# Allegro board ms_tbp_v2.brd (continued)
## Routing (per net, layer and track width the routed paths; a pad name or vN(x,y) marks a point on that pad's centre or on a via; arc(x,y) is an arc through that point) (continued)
ETH40G_B1_RX1N: length 29.1
  TOP w0.107: J8.21 100.01,5.18 arc(100.02,5.14) 100.04,5.1 100.16,4.98 arc(100.18,4.95) 100.19,4.91 100.19,3.55 v1(100,3.36)
  BOTTOM w0.107: J7.B5 119.97,5.59 arc(119.93,5.57) 119.89,5.56 119.67,5.56 arc(119.27,5.39) 119.11,5 119.11,4.15 arc(118.99,3.87) 118.7,3.75 116.94,3.75 arc(116.31,3.87) 115.77,4.23 113.35,6.65 arc(113,6.88) 112.58,6.97 101.38,6.97 arc(100.54,6.62) 100.19,5.78 100.19,3.81 arc(100.14,3.57) v1(100,3.36)
ETH40G_B1_RX1P: length 29.1
  TOP w0.107: v1(100.82,3.36) 100.63,3.55 100.63,4.91 arc(100.64,4.95) 100.66,4.98 100.78,5.1 arc(100.8,5.14) 100.81,5.18 J8.22
  BOTTOM w0.107: J7.A5 119.97,5.09 arc(119.93,5.11) 119.89,5.12 119.67,5.12 arc(119.58,5.09) 119.54,5 119.54,4.15 arc(119.3,3.56) 118.7,3.31 116.94,3.31 arc(116.14,3.47) 115.47,3.92 113.05,6.34 arc(112.83,6.48) 112.58,6.53 107.04,6.53 106.91,6.4 106.49,6.4 106.36,6.53 105.91,6.53 105.68,6.3 105.27,6.3 105.04,6.53 104.63,6.53 104.4,6.3 103.99,6.3 103.76,6.53 103.35,6.53 103.12,6.3 102.71,6.3 102.48,6.53 101.38,6.53 arc(100.85,6.31) 100.63,5.78 100.63,3.81 arc(100.68,3.57) v1(100.82,3.36)
ETH40G_B1_RX2N: length 43.9
  TOP w0.107: J8.15 102.01,9.64 arc(102.02,9.68) 102.04,9.72 102.16,9.84 arc(102.18,9.87) 102.19,9.91 102.19,12.87 arc(102.14,13.11) v1(102.01,13.31)
  BOTTOM w0.107: v1(102.01,13.31) 102.08,13.39 arc(102.17,13.52) 102.2,13.69 102.2,15.46 arc(102.52,16.22) 103.27,16.53 105.24,16.53 arc(106.18,16.72) 106.98,17.25 arc(109.67,19.04) 112.83,19.67 121.17,19.67 arc(122.2,19.47) 123.07,18.88 arc(123.5,18.24) 123.65,17.47 123.65,5.73 arc(123.71,5.6) 123.83,5.55 arc(123.92,5.57) 124.01,5.63 J7.B3
ETH40G_B1_RX2P: length 43.9
  TOP w0.107: J8.14 102.81,9.64 arc(102.8,9.68) 102.78,9.72 102.66,9.84 arc(102.64,9.87) 102.63,9.91 102.63,12.85 arc(102.68,13.1) v1(102.82,13.31)
  BOTTOM w0.107: J7.A3 124.02,5.04 arc(123.93,5.1) 123.83,5.12 arc(123.4,5.3) 123.22,5.73 123.22,17.47 arc(123.1,18.07) 122.76,18.58 arc(122.03,19.07) 121.17,19.24 117.79,19.24 117.51,18.96 117.08,18.96 116.8,19.24 115.73,19.24 115.47,18.98 115.12,18.98 114.87,19.24 112.83,19.24 arc(109.83,18.64) 107.29,16.94 arc(106.35,16.31) 105.24,16.09 104.43,16.09 104.2,15.86 103.79,15.86 103.56,16.09 103.27,16.09 arc(102.82,15.91) 102.64,15.46 102.64,15.26 102.72,15.18 102.72,14.66 102.64,14.58 102.64,13.69 arc(102.67,13.51) 102.77,13.36 v1(102.82,13.31)
ETH40G_B1_RX3N: length 34.9
  TOP w0.107: J8.24 102.41,5.13 102.59,4.95 102.59,2.3 arc(102.82,1.74) 103.37,1.52 104.02,1.52 arc(104.45,1.6) 104.82,1.85 104.83,1.86 arc(104.93,1.93) 105.06,1.95 105.59,1.95 arc(105.84,1.9) v1(106.05,1.76)
  LYR6 w0.112: v1(106.05,1.76) 106.22,1.94 arc(106.31,1.99) 106.41,2.01 106.62,2.01 arc(106.88,1.96) 107.11,1.81 arc(107.47,1.57) 107.89,1.49 113.17,1.49 arc(113.64,1.58) 114.03,1.85 115.26,3.07 arc(115.5,3.23) 115.78,3.29 126.99,3.29 arc(127.41,3.46) 127.58,3.89 127.58,6.14 arc(127.39,6.6) 126.93,6.79 arc(126.57,6.94) 126.42,7.31 J7.C2
ETH40G_B1_RX3P: length 34.9
  TOP w0.107: J8.25 103.21,5.13 103.03,4.95 103.03,4.74 103.22,4.55 103.22,4.08 103.03,3.89 103.03,2.3 arc(103.13,2.05) 103.37,1.95 104.02,1.95 arc(104.29,2) 104.51,2.16 104.52,2.17 arc(104.77,2.33) 105.06,2.39 105.59,2.39 arc(105.84,2.44) v1(106.05,2.58)
  LYR6 w0.112: v1(106.05,2.58) 106.09,2.54 arc(106.29,2.4) 106.52,2.36 106.62,2.36 arc(107.01,2.28) 107.35,2.05 arc(107.6,1.89) 107.89,1.83 108.51,1.83 108.68,2 108.98,2 109.15,1.83 110.4,1.83 110.63,2.06 111.05,2.06 111.28,1.83 111.69,1.83 111.92,2.06 112.34,2.06 112.57,1.83 113.17,1.83 arc(113.5,1.9) 113.79,2.09 115.02,3.32 arc(115.37,3.55) 115.78,3.63 116.03,3.63 116.26,3.86 116.64,3.86 116.87,3.63 117.29,3.63 117.52,3.86 117.91,3.86 118.14,3.63 118.55,3.63 118.79,3.86 119.17,3.86 119.4,3.63 121.35,3.63 121.58,3.86 122,3.86 122.23,3.63 122.64,3.63 122.87,3.86 123.29,3.86 123.52,3.63 125.05,3.63 125.28,3.86 125.7,3.86 125.93,3.63 126.99,3.63 arc(127.17,3.71) 127.24,3.89 127.24,6.14 arc(127.15,6.36) 126.93,6.45 arc(126.57,6.3) J7.B2
ETH40G_B1_SCL: length 67.8
  TOP w0.102: v1(92.77,35.17) 92.59,35.34 R82.2 ; v1(105.21,13.22) 105.21,12.78 104.66,12.23 104.66,11.37 105.2,10.84 105.2,8.67 J8.11
  LYR3 w0.13: J7.F4 121.24,10.36 121.24,3.82 120.92,3.5 117.77,3.5 116.39,4.88 116.39,5.32 117.6,6.53 117.6,11.29 116.36,12.53 114.18,12.53 113.14,13.57 106.12,13.57 105.77,13.22 v1(105.21,13.22) 105.56,13.58 105.56,19.39 98.66,26.29 98.66,29.27 v1(92.77,35.17)
ETH40G_B1_SDA: length 67.1
  TOP w0.102: J8.12 104.41,10.64 104.31,10.75 104.31,13.25 104.79,13.73 v1(104.79,14.32) ; R81.2 v1(92.67,33.95)
  LYR3 w0.13: v1(92.67,33.95) 98.25,28.36 98.25,25.57 104.79,19.03 v1(104.79,14.32) 104.58,14.1 104.58,12.94 105.02,12.49 105.64,12.49 106.25,13.11 113.12,13.11 114.03,12.21 116.16,12.21 117.28,11.09 117.28,6.63 116.11,5.45 116.11,4.62 117.52,3.21 121.23,3.21 121.58,3.56 121.58,9.3 J7.E4
ETH40G_B1_TX0N: length 17.9
  TOP w0.107: J8.37 112.81,5.18 arc(112.8,5.14) 112.78,5.1 112.66,4.98 arc(112.64,4.95) 112.63,4.91 112.63,4.36 arc(112.69,4.21) 112.84,4.15 113.04,4.15 113.22,4.33 113.53,4.33 113.7,4.15 113.95,4.15 arc(115.03,4.6) 115.48,5.68 115.48,5.8 115.19,6.09 115.19,6.48 115.48,6.77 115.48,6.98 arc(115.42,7.26) v1(115.27,7.49)
  LYR6 w0.112: J7.I6 118.42,15.61 arc(118.3,15.31) 118,15.19 arc(117.43,14.95) 117.2,14.39 117.2,13.07 116.97,12.85 116.97,12.5 117.2,12.27 117.2,11.86 116.96,11.63 116.96,11.22 117.2,10.99 117.2,10.78 arc(117.14,10.51) 116.99,10.28 115.99,9.28 arc(115.64,8.76) 115.52,8.14 115.52,8.09 arc(115.45,7.77) v1(115.27,7.49)
ETH40G_B1_TX0P: length 17.9
  TOP w0.107: J8.36 112.01,5.18 arc(112.02,5.14) 112.04,5.1 112.16,4.98 arc(112.18,4.95) 112.19,4.91 112.19,4.36 arc(112.38,3.91) 112.84,3.72 113.95,3.72 arc(115.34,4.29) 115.91,5.68 115.91,7.09 arc(115.96,7.3) v1(116.08,7.49)
  LYR6 w0.112: J7.H6 118.42,14.42 arc(118.3,14.72) 118,14.85 arc(117.67,14.71) 117.54,14.39 117.54,10.78 arc(117.46,10.38) 117.23,10.04 116.23,9.03 arc(115.95,8.62) 115.86,8.14 115.86,8.02 arc(115.92,7.74) v1(116.08,7.49)
ETH40G_B1_TX1N: length 15
  TOP w0.107: J8.2 112.41,9.64 arc(112.4,9.68) 112.38,9.72 112.26,9.84 arc(112.24,9.87) 112.23,9.91 112.23,11.44 arc(112.28,11.7) v1(112.43,11.93)
  BOTTOM w0.107: J7.C6 117.97,6.89 arc(117.93,6.87) 117.89,6.86 117.79,6.86 arc(117.71,6.89) 117.68,6.96 117.68,8.5 arc(117.48,9) 116.98,9.2 116.51,9.2 116.28,9.43 115.87,9.43 115.64,9.2 115.23,9.2 115,9.43 114.59,9.43 114.36,9.2 113.95,9.2 113.72,9.43 113.31,9.43 113.08,9.2 112.65,9.2 arc(112.36,9.32) 112.24,9.61 112.24,10.15 112.37,10.28 112.37,10.76 112.24,10.89 112.24,11.47 arc(112.29,11.72) v1(112.43,11.93)
ETH40G_B1_TX1P: length 15
  TOP w0.107: J8.3 111.61,9.64 arc(111.62,9.68) 111.64,9.72 111.76,9.84 arc(111.78,9.87) 111.79,9.91 111.79,11.5 arc(111.75,11.73) v1(111.62,11.93)
  BOTTOM w0.107: J7.B6 117.97,6.39 arc(117.93,6.41) 117.89,6.42 117.79,6.42 arc(117.4,6.58) 117.25,6.96 117.25,8.5 arc(117.17,8.69) 116.98,8.77 112.65,8.77 arc(112.06,9.01) 111.81,9.61 111.81,11.47 arc(111.76,11.72) v1(111.62,11.93)
ETH40G_B1_TX2N: length 43.3
  TOP w0.107: J8.34 110.41,5.13 110.23,4.95 110.23,4.58 109.3,3.66 arc(109.27,3.6) 109.25,3.54 109.25,3.38 arc(109.3,3.13) v1(109.45,2.91)
  LYR6 w0.112: J7.C4 122.42,7.31 arc(122.57,6.95) 122.92,6.81 123.04,6.81 arc(123.2,6.87) 123.26,7.02 123.26,17.06 arc(123.03,17.62) 122.46,17.86 121.67,17.86 121.44,17.63 120.87,17.63 120.64,17.86 120.22,17.86 119.99,17.63 119.43,17.63 119.2,17.86 117.79,17.86 arc(117.46,17.79) 117.19,17.6 116.57,16.99 arc(116.36,16.67) 116.28,16.29 116.28,16.08 116.51,15.85 116.51,15.51 116.28,15.28 116.28,14.87 116.47,14.68 116.47,14.26 116.28,14.07 116.28,13.4 arc(115.93,12.57) 115.09,12.22 arc(114.68,12.14) 114.34,11.9 114.24,11.81 arc(114.16,11.68) 114.13,11.54 114.13,11.21 114.36,10.99 114.36,10.66 114.13,10.43 114.13,10.12 114.36,9.89 114.36,9.59 114.13,9.36 114.13,9.13 114.3,8.97 114.3,8.64 114.13,8.47 114.13,7.93 114.13,7.92 114.13,7.15 114.13,7.15 arc(113.82,6.4) 113.08,6.1 112.7,6.1 112.51,5.91 112.09,5.91 111.9,6.1 111.48,6.1 111.27,5.88 110.9,5.88 110.69,6.1 110.47,6.1 arc(110.27,6.01) 110.18,5.81 110.18,5.2 arc(110.1,4.8) 109.88,4.46 109.52,4.11 arc(109.29,3.77) 109.21,3.37 arc(109.26,3.16) 109.37,2.98 v1(109.45,2.91)
ETH40G_B1_TX2P: length 43.3
  TOP w0.107: J8.33 109.61,5.13 109.79,4.95 109.79,4.76 109,3.97 arc(108.86,3.77) 108.82,3.54 108.82,3.36 arc(108.77,3.12) v1(108.63,2.91)
  LYR6 w0.112: J7.B4 122.42,5.97 arc(122.57,6.32) 122.92,6.46 123.04,6.46 arc(123.44,6.63) 123.6,7.02 123.6,17.06 arc(123.27,17.86) 122.46,18.2 117.79,18.2 arc(117.33,18.11) 116.94,17.85 116.33,17.23 arc(116.04,16.8) 115.94,16.29 115.94,13.4 arc(115.69,12.81) 115.09,12.56 arc(114.55,12.45) 114.09,12.15 114,12.05 arc(113.84,11.82) 113.79,11.54 113.79,7.15 arc(113.58,6.65) 113.08,6.44 110.47,6.44 arc(110.02,6.25) 109.84,5.81 109.84,5.2 arc(109.79,4.93) 109.63,4.71 109.28,4.35 arc(108.98,3.9) 108.87,3.37 arc(108.83,3.17) 108.72,3 v1(108.63,2.91)
ETH40G_B1_TX3N: length 43.8
  TOP w0.107: J8.5 110.01,9.64 arc(110,9.68) 109.98,9.72 109.86,9.84 arc(109.84,9.87) 109.83,9.91 109.83,15.42 arc(109.88,15.67) v1(110.02,15.88)
  LYR6 w0.112: J7.B1 128.95,5.51 129.06,5.51 arc(129.45,5.67) 129.61,6.06 129.61,6.35 129.38,6.58 129.38,7.1 129.61,7.33 129.61,8.05 129.38,8.28 129.38,8.76 129.61,8.99 129.61,10.58 129.38,10.81 129.38,11.25 129.61,11.48 129.61,11.89 129.38,12.12 129.38,12.56 129.61,12.79 129.61,15.54 arc(129.51,16.04) 129.23,16.46 126.55,19.14 arc(126.3,19.31) 126,19.37 124.77,19.37 124.54,19.14 124.02,19.14 123.79,19.37 119.44,19.37 119.21,19.14 118.65,19.14 118.42,19.37 116.27,19.37 116.04,19.14 115.63,19.14 115.4,19.37 114.43,19.37 114.2,19.14 113.79,19.14 113.56,19.37 113.08,19.37 arc(112.32,19.22) 111.68,18.79 111.05,18.16 111.05,18.01 110.75,17.7 110.6,17.7 109.84,16.94 arc(109.8,16.88) 109.78,16.8 109.78,16.44 arc(109.84,16.14) v1(110.02,15.88)
ETH40G_B1_TX3P: length 43.8
  TOP w0.107: J8.6 109.21,9.64 arc(109.22,9.68) 109.24,9.72 109.36,9.84 arc(109.38,9.87) 109.39,9.91 109.39,15.42 arc(109.34,15.67) v1(109.2,15.88)
  LYR6 w0.112: J7.A1 128.95,5.17 129.06,5.17 arc(129.69,5.43) 129.95,6.06 129.95,15.54 arc(129.83,16.17) 129.47,16.7 126.79,19.38 arc(126.43,19.63) 126,19.71 113.08,19.71 arc(112.19,19.53) 111.44,19.03 109.6,17.19 arc(109.48,17.01) 109.44,16.8 109.44,16.44 arc(109.38,16.14) v1(109.2,15.88)
ETH40G_B2_INT_N: length 57
  TOP w0.102: v1(313.19,36.77) R64.2 ; v1(326.47,4.81) 326.61,4.94 J20.28
  LYR3 w0.13: v1(319.45,4.37) 319.45,4.47 319.03,4.89 319.03,11.99 320.1,13.05 320.1,23.33 318.85,24.57 317.1,24.57 316.31,25.36 313.72,25.36 310.34,28.74 310.34,29.73 309.46,30.62 309.46,35.52 309.96,36.03 311.97,36.03 312.71,36.77 v1(313.19,36.77)
  LYR6 w0.13: v1(319.45,4.37) 319.45,4.75 319.89,5.19 319.89,7.05 320.1,7.26 325.99,7.26 326.21,7.04 326.21,5.07 v1(326.47,4.81)
ETH40G_B2_LPMODE: length 67.6
  TOP w0.102: v1(329.01,4.32) J20.31 ; R70.2 308.38,32.47 v1(307.47,32.47) ; R65.1 v1(309.99,38.16)
  LYR3 w0.13: v1(319.45,3.5) 319.33,3.62 318.32,3.62 316.44,5.5 316.44,13.58 319.34,16.47 319.34,22.87 318.09,24.12 316.28,24.12 315.42,24.98 312.27,24.98 309.9,27.36 309.9,28.3 308.85,29.35 308.85,31.1 v1(307.47,32.47) 307.68,32.68 307.68,37.22 308.62,38.16 v1(309.99,38.16)
  LYR6 w0.13: v1(319.45,3.5) 319.45,3.51 318.84,4.13 318.84,4.58 319.61,5.36 319.61,7.22 319.95,7.56 328.04,7.56 328.63,6.97 328.63,5.2 329.01,4.83 v1(329.01,4.32)
ETH40G_B2_MODPRS_N: length 61.2
  TOP w0.102: R66.1 v1(340.8,37.93) ; v1(337.76,5.56) 337.76,4.69 336.05,2.97 333.9,2.97 332.48,1.54 328.86,1.54 328.38,2.02 328.38,3.38 327.76,4 v1(326.06,4) 325.81,4.25 J20.27
  LYR3 w0.13: v1(340.8,37.93) 341.66,38.8 341.66,39.56 341.33,39.89 339.58,39.89 334.91,35.22 334.91,20.49 338.69,16.7 338.69,6.49 v1(337.76,5.56)
ETH40G_B2_MODSEL_N: length 42.8
  TOP w0.102: v1(313.14,40.96) R62.2 R63.1 ; v1(327.56,18.39) 327.56,15.74 329.39,13.91 329.39,11.95 328.61,11.17 J20.8
  LYR3 w0.13: v1(313.14,40.96) 313.88,40.96 315.68,39.15 315.68,34.63 324.05,26.26 324.05,20.85 326.5,18.39 v1(327.56,18.39)
ETH40G_B2_PRES_N: length 29.2
  TOP w0.102: R66.2 343.82,37.93 v1(343.87,37.88)
  LYR3 w0.13: v1(343.87,37.88) 342.25,37.88 338.87,34.51 338.87,21.73 342.37,18.22 342.37,15.39 J19.H5
ETH40G_B2_RESET_N: length 47.4
  TOP w0.102: R69.2 v1(313.39,39.56) ; J20.9 327.81,11.15 326.65,12.31 326.19,12.31 v1(325.83,12.66) ; R61.2 v1(310.2,32.58)
  LYR3 w0.13: v1(325.83,12.66) 325.83,13.69 324.93,14.6 323.02,14.6 320.83,16.78 320.83,20.86 320.78,20.91 320.78,25.79 319.27,27.31 312.54,27.31 311.49,28.36 311.49,31.29 v1(310.2,32.58) 310.2,32.61 311.39,33.79 311.39,34.58 312.96,36.15 313.39,36.15 313.9,36.66 313.9,39.05 v1(313.39,39.56)
ETH40G_B2_RX0N: length 36.2
  TOP w0.107: J20.18 320.61,9.64 arc(320.62,9.68) 320.64,9.72 320.76,9.84 arc(320.78,9.87) 320.79,9.91 320.79,10.99 arc(320.74,11.24) v1(320.6,11.45)
  BOTTOM w0.107: J19.F6 339.87,11.09 arc(339.91,11.07) 339.95,11.06 340.05,11.06 arc(340.15,11.1) 340.19,11.19 340.19,17.17 arc(340.12,17.52) 339.92,17.82 arc(339.45,18.02) 338.97,17.82 arc(338.32,17.39) 337.56,17.23 335.45,17.23 arc(334.87,17.12) 334.37,16.79 334.21,16.62 334.21,16.33 333.92,16.04 333.62,16.04 333.33,15.75 333.33,15.46 333.04,15.17 332.75,15.17 332.46,14.88 332.46,14.58 332.17,14.29 331.88,14.29 331.58,14 331.58,13.71 331.29,13.42 331,13.42 328.46,10.88 arc(325.89,9.16) 322.86,8.56 322.24,8.56 arc(321.22,8.98) 320.79,10.01 320.79,10.99 arc(320.74,11.24) v1(320.6,11.45)
ETH40G_B2_RX0P: length 36.2
  TOP w0.107: J20.17 321.41,9.64 arc(321.4,9.68) 321.38,9.72 321.26,9.84 arc(321.24,9.87) 321.23,9.91 321.23,10.99 arc(321.28,11.24) v1(321.42,11.45)
  BOTTOM w0.107: J19.E6 339.87,10.59 arc(339.91,10.61) 339.95,10.62 340.05,10.62 arc(340.46,10.79) 340.62,11.19 340.62,17.17 arc(340.52,17.69) 340.23,18.13 arc(339.45,18.45) 338.66,18.13 arc(338.16,17.79) 337.56,17.67 335.45,17.67 arc(334.7,17.52) 334.07,17.1 328.15,11.19 arc(325.73,9.56) 322.86,8.99 322.24,8.99 arc(321.52,9.29) 321.23,10.01 321.23,10.99 arc(321.28,11.24) v1(321.42,11.45)
ETH40G_B2_RX1N: length 29.1
  TOP w0.107: J20.21 321.01,5.18 arc(321.02,5.14) 321.04,5.1 321.16,4.98 arc(321.18,4.95) 321.19,4.91 321.19,3.55 v1(321,3.36)
  BOTTOM w0.107: J19.B5 340.97,5.59 arc(340.93,5.57) 340.89,5.56 340.67,5.56 arc(340.27,5.39) 340.11,5 340.11,4.15 arc(339.99,3.87) 339.7,3.75 337.94,3.75 arc(337.31,3.87) 336.77,4.23 334.35,6.65 arc(334,6.88) 333.58,6.97 322.38,6.97 arc(321.54,6.62) 321.19,5.78 321.19,3.81 arc(321.14,3.57) v1(321,3.36)
ETH40G_B2_RX1P: length 29.1
  TOP w0.107: v1(321.82,3.36) 321.63,3.55 321.63,4.91 arc(321.64,4.95) 321.66,4.98 321.78,5.1 arc(321.8,5.14) 321.81,5.18 J20.22
  BOTTOM w0.107: J19.A5 340.97,5.09 arc(340.93,5.11) 340.89,5.12 340.67,5.12 arc(340.58,5.09) 340.54,5 340.54,4.15 arc(340.3,3.56) 339.7,3.31 337.94,3.31 arc(337.14,3.47) 336.47,3.92 334.05,6.34 arc(333.83,6.48) 333.58,6.53 328.04,6.53 327.91,6.4 327.49,6.4 327.36,6.53 326.91,6.53 326.68,6.3 326.27,6.3 326.04,6.53 325.63,6.53 325.4,6.3 324.99,6.3 324.76,6.53 324.35,6.53 324.12,6.3 323.71,6.3 323.48,6.53 322.38,6.53 arc(321.85,6.31) 321.63,5.78 321.63,3.81 arc(321.68,3.57) v1(321.82,3.36)
ETH40G_B2_RX2N: length 43.9
  TOP w0.107: J20.15 323.01,9.64 arc(323.02,9.68) 323.04,9.72 323.16,9.84 arc(323.18,9.87) 323.19,9.91 323.19,12.87 arc(323.14,13.11) v1(323.01,13.31)
  BOTTOM w0.107: v1(323.01,13.31) 323.08,13.39 arc(323.17,13.52) 323.2,13.69 323.2,15.46 arc(323.52,16.22) 324.27,16.53 326.24,16.53 arc(327.18,16.72) 327.98,17.25 arc(330.67,19.04) 333.83,19.67 342.17,19.67 arc(343.2,19.47) 344.07,18.88 arc(344.5,18.24) 344.65,17.47 344.65,5.73 arc(344.71,5.6) 344.83,5.55 arc(344.92,5.57) 345.01,5.63 J19.B3
ETH40G_B2_RX2P: length 43.9
  TOP w0.107: J20.14 323.81,9.64 arc(323.8,9.68) 323.78,9.72 323.66,9.84 arc(323.64,9.87) 323.63,9.91 323.63,12.85 arc(323.68,13.1) v1(323.82,13.31)
  BOTTOM w0.107: v1(323.82,13.31) 323.77,13.36 arc(323.67,13.51) 323.64,13.69 323.64,14.58 323.72,14.66 323.72,15.18 323.64,15.26 323.64,15.46 arc(323.82,15.91) 324.27,16.09 324.56,16.09 324.79,15.86 325.2,15.86 325.43,16.09 326.24,16.09 arc(327.35,16.31) 328.29,16.94 arc(330.83,18.64) 333.83,19.24 335.87,19.24 336.12,18.98 336.47,18.98 336.73,19.24 337.8,19.24 338.08,18.96 338.51,18.96 338.79,19.24 342.17,19.24 arc(343.03,19.07) 343.76,18.58 arc(344.1,18.07) 344.22,17.47 344.22,5.73 arc(344.4,5.3) 344.83,5.12 arc(344.93,5.1) 345.02,5.04 J19.A3
ETH40G_B2_RX3N: length 34.9
  TOP w0.107: J20.24 323.41,5.13 323.59,4.95 323.59,2.3 arc(323.82,1.74) 324.37,1.52 325.02,1.52 arc(325.45,1.6) 325.82,1.85 325.83,1.86 arc(325.93,1.93) 326.06,1.95 326.59,1.95 arc(326.84,1.9) v1(327.05,1.76)
  LYR6 w0.112: J19.C2 347.42,7.31 arc(347.57,6.94) 347.93,6.79 arc(348.39,6.6) 348.58,6.14 348.58,3.89 arc(348.41,3.46) 347.99,3.29 336.78,3.29 arc(336.5,3.23) 336.26,3.07 335.03,1.85 arc(334.64,1.58) 334.17,1.49 328.89,1.49 arc(328.47,1.57) 328.11,1.81 arc(327.88,1.96) 327.62,2.01 327.41,2.01 arc(327.31,1.99) 327.22,1.94 v1(327.05,1.76)
ETH40G_B2_RX3P: length 34.9
  TOP w0.107: J20.25 324.21,5.13 324.03,4.95 324.03,4.74 324.22,4.55 324.22,4.08 324.03,3.89 324.03,2.3 arc(324.13,2.05) 324.37,1.95 325.02,1.95 arc(325.29,2) 325.51,2.16 325.52,2.17 arc(325.77,2.33) 326.06,2.39 326.59,2.39 arc(326.84,2.44) v1(327.05,2.58)
  LYR6 w0.112: v1(327.05,2.58) 327.09,2.54 arc(327.29,2.4) 327.52,2.36 327.62,2.36 arc(328.01,2.28) 328.35,2.05 arc(328.6,1.89) 328.89,1.83 329.51,1.83 329.68,2 329.98,2 330.15,1.83 331.4,1.83 331.63,2.06 332.05,2.06 332.28,1.83 332.69,1.83 332.92,2.06 333.34,2.06 333.57,1.83 334.17,1.83 arc(334.5,1.9) 334.79,2.09 336.02,3.32 arc(336.37,3.55) 336.78,3.63 337.03,3.63 337.26,3.86 337.64,3.86 337.87,3.63 338.29,3.63 338.52,3.86 338.91,3.86 339.14,3.63 339.55,3.63 339.79,3.86 340.17,3.86 340.4,3.63 342.35,3.63 342.58,3.86 343,3.86 343.23,3.63 343.64,3.63 343.87,3.86 344.29,3.86 344.52,3.63 346.05,3.63 346.28,3.86 346.7,3.86 346.93,3.63 347.99,3.63 arc(348.17,3.71) 348.24,3.89 348.24,6.14 arc(348.15,6.36) 347.93,6.45 arc(347.57,6.3) J19.B2
ETH40G_B2_SCL: length 73.9
  TOP w0.102: v1(313.49,35.37) R68.2 ; v1(323.5,18.6) 323.5,18.49 325.2,16.79 325.2,12.51 326.21,11.5 J20.11
  LYR3 w0.13: J19.F4 342.42,10.54 342.42,4.1 341.97,3.64 337.75,3.64 337.18,4.21 337.18,5.7 338.24,6.75 338.24,13.47 336.38,15.33 333.92,15.33 333.23,14.64 328.99,14.64 326.17,17.46 324.64,17.46 v1(323.5,18.6) 322.95,19.14 322.95,25.98 313.56,35.37 v1(313.49,35.37)
ETH40G_B2_SDA: length 69.4
  TOP w0.102: v1(313.06,33.97) R67.2 ; J20.12 325.41,11.79 324.95,12.26 324.95,14.44 323.46,15.93 v1(323.46,17.69)
  LYR3 w0.13: v1(313.06,33.97) 313.64,33.97 321.82,25.79 321.82,19.32 v1(323.46,17.69) 325.75,15.39 326.69,15.39 327.75,14.34 333.2,14.34 335.15,12.4 335.15,5.46 337.32,3.29 343.72,3.29 344.46,4.03 344.46,9.1 J19.E4
ETH40G_B2_TX0N: length 17.9
  TOP w0.107: J20.37 333.81,5.18 arc(333.8,5.14) 333.78,5.1 333.66,4.98 arc(333.64,4.95) 333.63,4.91 333.63,4.36 arc(333.69,4.21) 333.84,4.15 334.04,4.15 334.22,4.33 334.53,4.33 334.7,4.15 334.95,4.15 arc(336.03,4.6) 336.48,5.68 336.48,5.8 336.19,6.09 336.19,6.48 336.48,6.77 336.48,6.98 arc(336.42,7.26) v1(336.27,7.49)
  LYR6 w0.112: J19.I6 339.42,15.61 arc(339.3,15.31) 339,15.19 arc(338.43,14.95) 338.2,14.39 338.2,13.07 337.97,12.85 337.97,12.5 338.2,12.27 338.2,11.86 337.96,11.63 337.96,11.22 338.2,10.99 338.2,10.78 arc(338.14,10.51) 337.99,10.28 336.99,9.28 arc(336.64,8.76) 336.52,8.14 336.52,8.09 arc(336.45,7.77) v1(336.27,7.49)
ETH40G_B2_TX0P: length 17.9
  TOP w0.107: J20.36 333.01,5.18 arc(333.02,5.14) 333.04,5.1 333.16,4.98 arc(333.18,4.95) 333.19,4.91 333.19,4.36 arc(333.38,3.91) 333.84,3.72 334.95,3.72 arc(336.34,4.29) 336.91,5.68 336.91,7.09 arc(336.96,7.3) v1(337.08,7.49)
  LYR6 w0.112: J19.H6 339.42,14.42 arc(339.3,14.72) 339,14.85 arc(338.67,14.71) 338.54,14.39 338.54,10.78 arc(338.46,10.38) 338.23,10.04 337.23,9.03 arc(336.95,8.62) 336.86,8.14 336.86,8.02 arc(336.92,7.74) v1(337.08,7.49)
ETH40G_B2_TX1N: length 15
  TOP w0.107: J20.2 333.41,9.64 arc(333.4,9.68) 333.38,9.72 333.26,9.84 arc(333.24,9.87) 333.23,9.91 333.23,11.44 arc(333.28,11.7) v1(333.43,11.93)
  BOTTOM w0.107: J19.C6 338.97,6.89 arc(338.93,6.87) 338.89,6.86 338.79,6.86 arc(338.71,6.89) 338.68,6.96 338.68,8.5 arc(338.48,9) 337.98,9.2 337.51,9.2 337.28,9.43 336.87,9.43 336.64,9.2 336.23,9.2 336,9.43 335.59,9.43 335.36,9.2 334.95,9.2 334.72,9.43 334.31,9.43 334.08,9.2 333.65,9.2 arc(333.36,9.32) 333.24,9.61 333.24,10.15 333.37,10.28 333.37,10.76 333.24,10.89 333.24,11.47 arc(333.29,11.72) v1(333.43,11.93)
ETH40G_B2_TX1P: length 15
  TOP w0.107: J20.3 332.61,9.64 arc(332.62,9.68) 332.64,9.72 332.76,9.84 arc(332.78,9.87) 332.79,9.91 332.79,11.5 arc(332.75,11.73) v1(332.62,11.93)
  BOTTOM w0.107: J19.B6 338.97,6.39 arc(338.93,6.41) 338.89,6.42 338.79,6.42 arc(338.4,6.58) 338.25,6.96 338.25,8.5 arc(338.17,8.69) 337.98,8.77 333.65,8.77 arc(333.06,9.01) 332.81,9.61 332.81,11.47 arc(332.76,11.72) v1(332.62,11.93)
ETH40G_B2_TX2N: length 43.3
  TOP w0.107: J20.34 331.41,5.13 331.23,4.95 331.23,4.58 330.3,3.66 arc(330.27,3.6) 330.25,3.54 330.25,3.38 arc(330.3,3.13) v1(330.45,2.91)
  LYR6 w0.112: v1(330.45,2.91) 330.37,2.98 arc(330.26,3.16) 330.21,3.37 arc(330.29,3.77) 330.52,4.11 330.88,4.46 arc(331.1,4.8) 331.18,5.2 331.18,5.81 arc(331.27,6.01) 331.47,6.1 331.69,6.1 331.9,5.88 332.27,5.88 332.48,6.1 332.9,6.1 333.09,5.91 333.51,5.91 333.7,6.1 334.08,6.1 arc(334.82,6.4) 335.13,7.15 335.13,7.15 335.13,7.92 335.13,7.93 335.13,8.47 335.3,8.64 335.3,8.97 335.13,9.13 335.13,9.36 335.36,9.59 335.36,9.89 335.13,10.12 335.13,10.43 335.36,10.66 335.36,10.99 335.13,11.21 335.13,11.54 arc(335.16,11.68) 335.24,11.81 335.34,11.9 arc(335.68,12.14) 336.09,12.22 arc(336.93,12.57) 337.28,13.4 337.28,14.07 337.47,14.26 337.47,14.68 337.28,14.87 337.28,15.28 337.51,15.51 337.51,15.85 337.28,16.08 337.28,16.29 arc(337.36,16.67) 337.57,16.99 338.19,17.6 arc(338.46,17.79) 338.79,17.86 340.2,17.86 340.43,17.63 340.99,17.63 341.22,17.86 341.64,17.86 341.87,17.63 342.44,17.63 342.67,17.86 343.46,17.86 arc(344.03,17.62) 344.26,17.06 344.26,7.02 arc(344.2,6.87) 344.04,6.81 343.92,6.81 arc(343.57,6.95) 343.42,7.31 J19.C4
ETH40G_B2_TX2P: length 43.3
  TOP w0.107: J20.33 330.61,5.13 330.79,4.95 330.79,4.76 330,3.97 arc(329.86,3.77) 329.82,3.54 329.82,3.36 arc(329.77,3.12) v1(329.63,2.91)
  LYR6 w0.112: J19.B4 343.42,5.97 arc(343.57,6.32) 343.92,6.46 344.04,6.46 arc(344.44,6.63) 344.6,7.02 344.6,17.06 arc(344.27,17.86) 343.46,18.2 338.79,18.2 arc(338.33,18.11) 337.94,17.85 337.33,17.23 arc(337.04,16.8) 336.94,16.29 336.94,13.4 arc(336.69,12.81) 336.09,12.56 arc(335.55,12.45) 335.09,12.15 335,12.05 arc(334.84,11.82) 334.79,11.54 334.79,7.15 arc(334.58,6.65) 334.08,6.44 331.47,6.44 arc(331.02,6.25) 330.84,5.81 330.84,5.2 arc(330.79,4.93) 330.63,4.71 330.28,4.35 arc(329.98,3.9) 329.87,3.37 arc(329.83,3.17) 329.72,3 v1(329.63,2.91)
ETH40G_B2_TX3N: length 43.8
  TOP w0.107: J20.5 331.01,9.64 arc(331,9.68) 330.98,9.72 330.86,9.84 arc(330.84,9.87) 330.83,9.91 330.83,15.42 arc(330.88,15.67) v1(331.02,15.88)
  LYR6 w0.112: J19.B1 349.95,5.51 350.06,5.51 arc(350.45,5.67) 350.61,6.06 350.61,6.35 350.38,6.58 350.38,7.1 350.61,7.33 350.61,8.05 350.38,8.28 350.38,8.76 350.61,8.99 350.61,10.58 350.38,10.81 350.38,11.25 350.61,11.48 350.61,11.89 350.38,12.12 350.38,12.56 350.61,12.79 350.61,15.54 arc(350.51,16.04) 350.23,16.46 347.55,19.14 arc(347.3,19.31) 347,19.37 345.77,19.37 345.54,19.14 345.02,19.14 344.79,19.37 340.44,19.37 340.21,19.14 339.65,19.14 339.42,19.37 337.27,19.37 337.04,19.14 336.63,19.14 336.4,19.37 335.43,19.37 335.2,19.14 334.79,19.14 334.56,19.37 334.08,19.37 arc(333.32,19.22) 332.68,18.79 332.05,18.16 332.05,18.01 331.75,17.7 331.6,17.7 330.84,16.94 arc(330.8,16.88) 330.78,16.8 330.78,16.44 arc(330.84,16.14) v1(331.02,15.88)
ETH40G_B2_TX3P: length 43.8
  TOP w0.107: J20.6 330.21,9.64 arc(330.22,9.68) 330.24,9.72 330.36,9.84 arc(330.38,9.87) 330.39,9.91 330.39,15.42 arc(330.34,15.67) v1(330.2,15.88)
  LYR6 w0.112: J19.A1 349.95,5.17 350.06,5.17 arc(350.69,5.43) 350.95,6.06 350.95,15.54 arc(350.83,16.17) 350.47,16.7 347.79,19.38 arc(347.43,19.63) 347,19.71 334.08,19.71 arc(333.19,19.53) 332.44,19.03 330.6,17.19 arc(330.48,17.01) 330.44,16.8 330.44,16.44 arc(330.38,16.14) v1(330.2,15.88)
JBOD_B1_MATED_N: length 14.8
  TOP w0.102: R1.2 177.74,5.41 175.9,3.57 170.7,3.57 169.6,4.66 169.6,5.12 J11.B4
JBOD_B2_MATED_N: length 15.1
  TOP w0.102: J23.B4 390.59,5.13 390.6,5.11 390.6,4.43 391.45,3.58 396.45,3.58 396.81,3.94 396.81,4.4 397.56,5.15 R71.2
MEZZ_B1_EN: length 41
  TOP w0.127: J2.157 v1(47.38,31.74)
  LYR4 w0.13: J1.H5 22.89,15.43 22.89,26.86 24.75,28.71 38.16,28.71 42.22,32.78 45.85,32.78 46.89,31.74 v1(47.38,31.74)
MEZZ_B1_SCL: length 40.6
  TOP w0.127: J2.156 v1(46.11,31.74)
  LYR4 w0.13: v1(46.11,31.74) 45.38,32.47 44.51,32.47 44.1,32.07 44.1,31.37 43.82,31.09 41.42,31.09 38.5,28.17 25.29,28.17 23.15,26.02 23.15,14.31 22,13.17 J1.G5
MEZZ_B1_SDA: length 38
  TOP w0.127: J2.158 v1(48.65,31.74)
  LYR4 w0.13: v1(48.65,31.74) 48.6,31.74 48.09,31.23 44.79,31.23 44.23,30.67 44.23,30.21 43.88,29.86 41.31,29.86 39.29,27.83 26.41,27.83 24.9,26.33 24.9,16.74 J1.I4
MEZZ_B2_EN: length 41
  TOP w0.127: J14.157 v1(268.38,31.74)
  LYR4 w0.13: J13.H5 243.89,15.43 243.89,26.86 245.75,28.71 259.16,28.71 263.22,32.78 266.85,32.78 267.89,31.74 v1(268.38,31.74)
MEZZ_B2_SCL: length 40.6
  TOP w0.127: J14.156 v1(267.11,31.74)
  LYR4 w0.13: J13.G5 243,13.17 244.15,14.31 244.15,26.02 246.29,28.17 259.5,28.17 262.42,31.09 264.82,31.09 265.1,31.37 265.1,32.07 265.51,32.47 266.38,32.47 v1(267.11,31.74)
MEZZ_B2_SDA: length 38
  TOP w0.127: J14.158 v1(269.65,31.74)
  LYR4 w0.13: J13.I4 245.9,16.74 245.9,26.33 247.41,27.83 260.29,27.83 262.31,29.86 264.88,29.86 265.23,30.21 265.23,30.67 265.8,31.24 269.1,31.24 269.6,31.74 v1(269.65,31.74)
MEZZ_PRESENT_B1_N: length 48.5
  TOP w0.127: J2.160 v1(51.19,31.74)
  LYR4 w0.13: v1(51.19,31.74) 50.58,32.35 46.84,32.35 46.06,33.13 41.87,33.13 37.93,29.2 22.31,29.2 18.98,25.87 18.98,15.46 20,14.44 J1.H6
MEZZ_PRESENT_B2_N: length 48.5
  TOP w0.127: J14.160 v1(272.19,31.74)
  LYR4 w0.13: J13.H6 241,14.44 239.98,15.46 239.98,25.87 243.31,29.2 258.93,29.2 262.87,33.13 267.06,33.13 267.84,32.35 271.58,32.35 v1(272.19,31.74)
PCIE_B2T_B1_TX_DN<0>: length 46.1
  TOP w0.127: J2.125 v1(47.38,26.66)
  BOTTOM w0.127: J1.L8 16.55,19.49 16.67,19.49 16.85,19.67 16.85,26.23 23.58,32.96 34.86,32.96 41.23,26.58 42.27,26.58 43.13,27.44 45.23,27.44 45.64,27.04 45.64,26.32 45.79,26.18 46.9,26.18 v1(47.38,26.66)
PCIE_B2T_B1_TX_DN<1>: length 46.1
  TOP w0.127: J2.110 v1(48.65,24.12)
  BOTTOM w0.127: J1.K7 18.55,18.19 18.76,18.19 18.85,18.29 18.85,26.33 24.26,31.74 34.02,31.74 40.85,24.9 46.5,24.9 46.91,24.5 46.91,23.78 47.06,23.64 48.17,23.64 v1(48.65,24.12)
PCIE_B2T_B1_TX_DN<2>: length 41.3
  TOP w0.127: J2.93 v1(47.38,21.58)
  BOTTOM w0.127: J1.L6 20.55,19.49 20.67,19.49 20.86,19.67 20.86,24.81 20.86,24.82 20.86,26.12 25.23,30.49 33.41,30.49 40.9,23 43.47,23 44.12,22.36 45.23,22.36 45.64,21.96 45.64,21.24 45.79,21.1 46.9,21.1 v1(47.38,21.58)
PCIE_B2T_B1_TX_DN<3>: length 42.4
  TOP w0.127: J2.78 v1(48.65,19.04)
  BOTTOM w0.127: v1(48.65,19.04) 48.17,18.56 47.06,18.56 46.91,18.7 46.91,19.42 46.5,19.82 41.26,19.82 38.44,22.64 38.44,23.33 32.54,29.22 32.54,29.22 31.53,29.22 31.53,29.22 25.84,29.22 23.02,26.4 22.84,26.23 22.84,18.36 22.67,18.19 22.55,18.19 J1.K5
PCIE_B2T_B1_TX_DN<4>: length 37.8
  TOP w0.127: J2.61 v1(47.38,16.5)
  BOTTOM w0.127: J1.L4 24.55,19.49 24.66,19.49 24.85,19.68 24.85,25.95 26.91,28 31.63,28 35.97,23.66 35.97,22.69 40.75,17.92 42.95,17.92 43.59,17.28 45.23,17.28 45.64,16.88 45.64,16.16 45.79,16.02 46.9,16.02 v1(47.38,16.5)
PCIE_B2T_B1_TX_DN<5>: length 38.6
  TOP w0.127: J2.46 v1(48.65,13.96)
  BOTTOM w0.127: v1(48.65,13.96) 48.17,13.48 47.06,13.48 46.91,13.62 46.91,14.34 46.5,14.74 43.3,14.74 41.5,16.54 40.29,16.54 33.79,23.04 33.79,23.99 31,26.78 27.53,26.78 26.86,26.11 26.86,26.1 26.86,26.1 26.86,18.35 26.69,18.19 26.55,18.19 J1.K3
PCIE_B2T_B1_TX_DN<6>: length 33.4
  TOP w0.127: J2.29 v1(47.38,11.42)
  BOTTOM w0.127: v1(47.38,11.42) 46.9,10.94 45.79,10.94 45.64,11.08 45.64,11.8 45.23,12.2 44.4,12.2 43.75,12.85 41.99,12.85 41.7,13.15 41.7,13.37 31.14,23.92 31.14,24.81 30.47,25.48 30.01,25.48 30,25.49 29.47,25.49 28.86,24.87 28.86,19.61 28.74,19.49 28.55,19.49 J1.L2
PCIE_B2T_B1_TX_DN<7>: length 24.9
  TOP w0.127: J2.14 v1(48.65,8.88)
  BOTTOM w0.127: v1(48.65,8.88) 48.17,8.4 47.06,8.4 46.91,8.54 46.91,9.26 46.5,9.66 42.8,9.66 40.52,11.94 40.52,12.7 37.66,15.56 35.29,15.56 32.65,18.19 30.55,18.19 J1.K1
PCIE_B2T_B1_TX_DN<8>: length 44.5
  TOP w0.127: J2.127 v1(49.92,26.66)
  LYR6 w0.127: v1(49.92,26.66) 49.43,26.17 48.28,26.17 48.17,26.29 48.17,27.08 47.79,27.45 43.23,27.45 42.35,26.57 40.2,26.57 34.77,32 21.27,32 16.87,27.6 16.87,23.89 16.67,23.69 16.55,23.69 J1.O8
PCIE_B2T_B1_TX_DN<9>: length 44.2
  TOP w0.127: J2.112 v1(51.19,24.12)
  LYR6 w0.127: J1.N7 18.55,22.39 18.76,22.39 18.84,22.46 18.84,26.98 22.82,30.96 34.34,30.96 40.39,24.91 49.06,24.91 49.44,24.54 49.44,23.75 49.55,23.63 50.7,23.63 v1(51.19,24.12)
PCIE_B2T_B1_TX_DN<10>: length 39.5
  TOP w0.127: J2.95 v1(49.92,21.58)
  LYR6 w0.127: v1(49.92,21.58) 49.43,21.09 48.28,21.09 48.17,21.21 48.17,22 47.79,22.37 43.45,22.37 42.82,23 40.8,23 37.09,26.71 35.51,26.71 32.3,29.92 24.4,29.92 20.85,26.37 20.85,23.74 20.79,23.69 20.55,23.69 J1.O6
PCIE_B2T_B1_TX_DN<11>: length 40.2
  TOP w0.127: J2.80 v1(51.19,19.04)
  LYR6 w0.127: v1(51.19,19.04) 50.7,18.55 49.55,18.55 49.44,18.67 49.44,19.46 49.06,19.83 40.87,19.83 31.82,28.88 25.42,28.88 22.85,26.31 22.85,22.5 22.74,22.39 22.55,22.39 J1.N5
PCIE_B2T_B1_TX_DN<12>: length 36.3
  TOP w0.127: J2.63 v1(49.92,16.5)
  LYR6 w0.127: J1.O4 24.55,23.69 24.7,23.69 24.86,23.84 24.86,26.35 26.33,27.81 31.36,27.81 35.24,23.94 35.24,23.06 40.37,17.92 43.16,17.92 43.79,17.29 47.79,17.29 48.17,16.92 48.17,16.13 48.28,16.01 49.43,16.01 v1(49.92,16.5)
PCIE_B2T_B1_TX_DN<13>: length 38.1
  TOP w0.127: J2.48 v1(51.19,13.96)
  LYR6 w0.127: v1(51.19,13.96) 50.7,13.47 49.55,13.47 49.44,13.59 49.44,14.38 49.06,14.75 40.06,14.75 34.07,20.74 34.07,23.53 30.83,26.77 27.53,26.77 26.87,26.11 26.87,22.47 26.79,22.39 26.55,22.39 J1.N3
PCIE_B2T_B1_TX_DN<14>: length 33.4
  TOP w0.127: J2.31 v1(49.92,11.42)
  LYR6 w0.127: v1(49.92,11.42) 49.43,10.93 48.28,10.93 48.17,11.05 48.17,11.84 47.79,12.21 43.69,12.21 43.07,12.83 39.41,12.83 32.76,19.48 32.76,23.27 30.53,25.5 29.32,25.5 28.81,24.99 28.81,23.81 28.68,23.69 28.55,23.69 J1.O2
PCIE_B2T_B1_TX_DN<15>: length 37.9
  TOP w0.127: J2.16 v1(51.19,8.88)
  LYR6 w0.127: v1(51.19,8.88) 50.7,8.39 49.52,8.39 49.15,8.03 49.15,7.05 48.52,6.41 34.15,6.41 31.67,8.9 31.67,16.51 31.5,16.68 31.31,16.87 31.31,21.88 30.8,22.39 30.55,22.39 J1.N1
PCIE_B2T_B1_TX_DP<0>: length 46.1
  TOP w0.127: J2.117 v1(47.38,25.39)
  BOTTOM w0.127: v1(47.38,25.39) 46.9,25.87 45.66,25.87 45.33,26.2 45.33,26.91 45.11,27.14 43.25,27.14 42.39,26.28 41.1,26.28 34.73,32.65 23.7,32.65 17.15,26.1 17.15,19.54 16.8,19.19 16.55,19.19 J1.K8
PCIE_B2T_B1_TX_DP<1>: length 46.1
  TOP w0.127: J2.102 v1(48.65,22.85)
  BOTTOM w0.127: J1.J7 18.55,17.89 18.88,17.89 19.16,18.16 19.16,26.2 24.39,31.43 33.89,31.43 40.73,24.6 46.38,24.6 46.6,24.37 46.6,23.66 46.93,23.33 48.17,23.33 v1(48.65,22.85)
PCIE_B2T_B1_TX_DP<2>: length 41.3
  TOP w0.127: J2.85 v1(47.38,20.31)
  BOTTOM w0.127: v1(47.38,20.31) 46.9,20.79 45.66,20.79 45.33,21.12 45.33,21.83 45.11,22.06 43.99,22.06 43.35,22.7 40.77,22.7 33.28,30.19 25.36,30.19 21.17,26 21.17,24.69 21.16,24.69 21.16,19.55 20.8,19.19 20.55,19.19 J1.K6
PCIE_B2T_B1_TX_DP<3>: length 42.4
  TOP w0.127: J2.70 v1(48.65,17.77)
  BOTTOM w0.127: v1(48.65,17.77) 48.17,18.25 46.93,18.25 46.6,18.58 46.6,19.29 46.38,19.52 41.13,19.52 38.13,22.52 38.13,23.2 32.42,28.92 32.41,28.92 25.97,28.92 23.15,26.1 23.15,18.23 22.8,17.89 22.55,17.89 J1.J5
PCIE_B2T_B1_TX_DP<4>: length 37.8
  TOP w0.127: J2.53 v1(47.38,15.23)
  BOTTOM w0.127: J1.K4 24.55,19.19 24.78,19.19 25.15,19.56 25.15,25.82 27.03,27.7 31.5,27.7 35.67,23.53 35.67,22.57 40.62,17.61 42.83,17.61 43.46,16.98 45.11,16.98 45.33,16.75 45.33,16.04 45.66,15.71 46.9,15.71 v1(47.38,15.23)
PCIE_B2T_B1_TX_DP<5>: length 38.6
  TOP w0.127: J2.38 v1(48.65,12.69)
  BOTTOM w0.127: J1.J3 26.55,17.89 26.82,17.89 27.16,18.23 27.16,25.97 27.16,25.97 27.16,25.99 27.65,26.48 30.87,26.48 33.48,23.86 33.48,22.91 40.17,16.23 41.38,16.23 43.17,14.44 46.38,14.44 46.6,14.21 46.6,13.5 46.93,13.17 48.17,13.17 v1(48.65,12.69)
PCIE_B2T_B1_TX_DP<6>: length 33.4
  TOP w0.127: J2.21 v1(47.38,10.15)
  BOTTOM w0.127: v1(47.38,10.15) 46.9,10.63 45.66,10.63 45.33,10.96 45.33,11.67 45.11,11.9 44.28,11.9 43.63,12.55 41.87,12.55 41.39,13.02 41.39,13.24 30.84,23.79 30.84,24.69 30.35,25.18 29.88,25.18 29.88,25.18 29.6,25.18 29.16,24.75 29.16,19.48 28.86,19.19 28.55,19.19 J1.K2
PCIE_B2T_B1_TX_DP<7>: length 24.9
  TOP w0.127: J2.6 v1(48.65,7.61)
  BOTTOM w0.127: J1.J1 30.55,17.89 32.53,17.89 35.16,15.25 37.53,15.25 40.21,12.57 40.21,11.82 42.67,9.36 46.38,9.36 46.6,9.13 46.6,8.42 46.93,8.09 48.17,8.09 v1(48.65,7.61)
PCIE_B2T_B1_TX_DP<8>: length 44.5
  TOP w0.127: J2.119 v1(49.92,25.39)
  LYR6 w0.127: v1(49.92,25.39) 49.43,25.88 48.16,25.88 47.87,26.16 47.87,26.96 47.67,27.16 43.35,27.16 42.47,26.28 40.08,26.28 34.65,31.71 21.39,31.71 17.16,27.48 17.16,23.76 16.79,23.39 16.55,23.39 J1.N8
PCIE_B2T_B1_TX_DP<9>: length 44.2
  TOP w0.127: J2.104 v1(51.19,22.85)
  LYR6 w0.127: J1.M7 18.55,22.09 18.88,22.09 19.13,22.34 19.13,26.86 22.94,30.67 34.21,30.67 40.26,24.62 48.94,24.62 49.14,24.42 49.14,23.62 49.43,23.34 50.7,23.34 v1(51.19,22.85)
PCIE_B2T_B1_TX_DP<10>: length 39.5
  TOP w0.127: J2.87 v1(49.92,20.31)
  LYR6 w0.127: v1(49.92,20.31) 49.43,20.8 48.16,20.8 47.87,21.08 47.87,21.88 47.67,22.08 43.33,22.08 42.7,22.71 40.68,22.71 36.97,26.42 35.39,26.42 32.18,29.63 24.52,29.63 21.14,26.25 21.14,23.62 20.91,23.39 20.55,23.39 J1.N6
PCIE_B2T_B1_TX_DP<11>: length 40.2
  TOP w0.127: J2.72 v1(51.19,17.77)
  LYR6 w0.127: J1.M5 22.55,22.09 22.86,22.09 23.15,22.38 23.15,26.19 25.54,28.59 31.7,28.59 40.75,19.54 48.94,19.54 49.14,19.34 49.14,18.54 49.43,18.26 50.7,18.26 v1(51.19,17.77)
PCIE_B2T_B1_TX_DP<12>: length 36.3
  TOP w0.127: J2.55 v1(49.92,15.23)
  LYR6 w0.127: v1(49.92,15.23) 49.43,15.72 48.16,15.72 47.87,16 47.87,16.8 47.67,17 43.67,17 43.04,17.63 40.25,17.63 34.94,22.94 34.94,23.82 31.24,27.52 26.45,27.52 25.15,26.23 25.15,23.72 24.82,23.39 24.55,23.39 J1.N4
PCIE_B2T_B1_TX_DP<13>: length 38.1
  TOP w0.127: J2.40 v1(51.19,12.69)
  LYR6 w0.127: v1(51.19,12.69) 50.7,13.18 49.43,13.18 49.14,13.46 49.14,14.26 48.94,14.46 39.93,14.46 33.78,20.62 33.78,23.41 30.71,26.48 27.65,26.48 27.16,25.99 27.16,22.35 26.91,22.09 26.55,22.09 J1.M3
PCIE_B2T_B1_TX_DP<14>: length 33.4
  TOP w0.127: J2.23 v1(49.92,10.15)
  LYR6 w0.127: J1.N2 28.55,23.39 28.8,23.39 29.1,23.69 29.1,24.87 29.44,25.21 30.4,25.21 32.47,23.15 32.47,19.36 39.29,12.54 42.95,12.54 43.56,11.92 47.67,11.92 47.87,11.72 47.87,10.92 48.16,10.64 49.43,10.64 v1(49.92,10.15)
PCIE_B2T_B1_TX_DP<15>: length 37.9
  TOP w0.127: J2.8 v1(51.19,7.61)
  LYR6 w0.127: v1(51.19,7.61) 50.7,8.1 49.64,8.1 49.45,7.91 49.45,6.93 48.64,6.12 34.03,6.12 31.38,8.78 31.38,16.39 31.02,16.75 31.02,21.76 30.68,22.09 30.55,22.09 J1.M1
PCIE_B2T_B2_TX_DN<0>: length 46.1
  TOP w0.127: J14.125 v1(268.38,26.66)
  BOTTOM w0.127: J13.L8 237.55,19.49 237.67,19.49 237.85,19.67 237.85,26.23 244.58,32.96 255.86,32.96 262.23,26.58 263.27,26.58 264.13,27.44 266.23,27.44 266.64,27.04 266.64,26.32 266.79,26.18 267.9,26.18 v1(268.38,26.66)
PCIE_B2T_B2_TX_DN<1>: length 46.1
  TOP w0.127: J14.110 v1(269.65,24.12)
  BOTTOM w0.127: v1(269.65,24.12) 269.17,23.64 268.06,23.64 267.91,23.78 267.91,24.5 267.5,24.9 261.85,24.9 255.02,31.74 245.26,31.74 239.85,26.33 239.85,18.29 239.76,18.19 239.55,18.19 J13.K7
PCIE_B2T_B2_TX_DN<2>: length 41.3
  TOP w0.127: J14.93 v1(268.38,21.58)
  BOTTOM w0.127: v1(268.38,21.58) 267.9,21.1 266.79,21.1 266.64,21.24 266.64,21.96 266.23,22.36 265.12,22.36 264.47,23 261.9,23 254.41,30.49 246.23,30.49 241.86,26.12 241.86,24.82 241.86,24.81 241.86,19.67 241.67,19.49 241.55,19.49 J13.L6
PCIE_B2T_B2_TX_DN<3>: length 42
  TOP w0.127: J14.78 v1(269.65,19.04)
  BOTTOM w0.127: J13.K5 243.55,18.19 243.67,18.19 243.84,18.36 243.84,25.97 243.84,26.23 246.84,29.22 252.53,29.22 252.53,29.22 253.54,29.22 262.94,19.82 267.5,19.82 267.91,19.42 267.91,18.7 268.06,18.56 269.17,18.56 v1(269.65,19.04)
PCIE_B2T_B2_TX_DN<4>: length 37.3
  TOP w0.127: J14.61 v1(268.38,16.5)
  BOTTOM w0.127: J13.L4 245.55,19.49 245.66,19.49 245.85,19.68 245.85,25.95 247.91,28 252.63,28 262.71,17.92 263.95,17.92 264.59,17.28 266.23,17.28 266.64,16.88 266.64,16.16 266.79,16.02 267.9,16.02 v1(268.38,16.5)
PCIE_B2T_B2_TX_DN<5>: length 38
  TOP w0.127: J14.46 v1(269.65,13.96)
  BOTTOM w0.127: v1(269.65,13.96) 269.17,13.48 268.06,13.48 267.91,13.62 267.91,14.34 267.5,14.74 264.17,14.74 252.13,26.78 248.53,26.78 247.86,26.11 247.86,26.1 247.86,26.1 247.86,18.35 247.69,18.19 247.55,18.19 J13.K3
PCIE_B2T_B2_TX_DN<6>: length 33.1
  TOP w0.127: J14.29 v1(268.38,11.42)
  BOTTOM w0.127: J13.L2 249.55,19.49 249.74,19.49 249.86,19.61 249.86,24.87 250.47,25.49 251,25.49 251.01,25.48 251.47,25.48 252.14,24.81 252.14,24.2 258.79,17.56 259.11,17.56 263.17,13.5 264.1,13.5 265.4,12.2 266.23,12.2 266.64,11.8 266.64,11.08 266.79,10.94 267.9,10.94 v1(268.38,11.42)
PCIE_B2T_B2_TX_DN<7>: length 25.2
  TOP w0.127: J14.14 v1(269.65,8.88)
  BOTTOM w0.127: v1(269.65,8.88) 269.17,8.4 268.06,8.4 267.91,8.54 267.91,9.26 267.5,9.66 263.8,9.66 262.27,11.19 262.27,12.45 258.83,15.89 256.96,15.89 254.66,18.19 251.55,18.19 J13.K1
PCIE_B2T_B2_TX_DN<8>: length 44.5
  TOP w0.127: J14.127 v1(270.92,26.66)
  LYR6 w0.127: v1(270.92,26.66) 270.43,26.17 269.28,26.17 269.18,26.27 269.18,27.07 268.8,27.44 264.22,27.44 263.35,26.57 261.2,26.57 255.77,32 242.27,32 237.87,27.6 237.87,23.89 237.67,23.69 237.55,23.69 J13.O8
PCIE_B2T_B2_TX_DN<9>: length 44.2
  TOP w0.127: J14.112 v1(272.19,24.12)
  LYR6 w0.127: J13.N7 239.55,22.39 239.76,22.39 239.84,22.46 239.84,26.98 243.82,30.96 255.34,30.96 261.4,24.9 270.07,24.9 270.44,24.53 270.44,23.74 270.55,23.63 271.7,23.63 v1(272.19,24.12)
PCIE_B2T_B2_TX_DN<10>: length 39.5
  TOP w0.127: J14.95 v1(270.92,21.58)
  LYR6 w0.127: v1(270.92,21.58) 270.43,21.09 269.28,21.09 269.18,21.2 269.18,21.99 268.8,22.36 264.46,22.36 263.82,23 261.8,23 258.09,26.71 256.51,26.71 253.3,29.92 245.4,29.92 241.85,26.37 241.85,23.74 241.79,23.69 241.55,23.69 J13.O6
PCIE_B2T_B2_TX_DN<11>: length 40.2
  TOP w0.127: J14.80 v1(272.19,19.04)
  LYR6 w0.127: J13.N5 243.55,22.39 243.74,22.39 243.85,22.5 243.85,26.31 246.42,28.88 252.82,28.88 261.88,19.82 270.08,19.82 270.45,19.45 270.45,18.66 270.55,18.55 271.7,18.55 v1(272.19,19.04)
PCIE_B2T_B2_TX_DN<12>: length 36.3
  TOP w0.127: J14.63 v1(270.92,16.5)
  LYR6 w0.127: v1(270.92,16.5) 270.43,16.01 269.28,16.01 269.18,16.11 269.18,16.91 268.8,17.28 264.8,17.28 264.19,17.89 261.4,17.89 256.24,23.06 256.24,23.94 252.36,27.81 247.33,27.81 245.86,26.35 245.86,23.84 245.7,23.69 245.55,23.69 J13.O4
PCIE_B2T_B2_TX_DN<13>: length 38.1
  TOP w0.127: J14.48 v1(272.19,13.96)
  LYR6 w0.127: v1(272.19,13.96) 271.7,13.47 270.55,13.47 270.45,13.58 270.45,14.37 270.07,14.74 264.1,14.74 263.54,15.3 260.51,15.3 255.07,20.74 255.07,23.53 251.83,26.77 248.53,26.77 247.87,26.11 247.87,22.47 247.79,22.39 247.55,22.39 J13.N3
PCIE_B2T_B2_TX_DN<14>: length 33.4
  TOP w0.127: J14.31 v1(270.92,11.42)
  LYR6 w0.127: v1(270.92,11.42) 270.43,10.93 269.28,10.93 269.18,11.03 269.18,11.83 268.8,12.2 264.7,12.2 264.07,12.83 260.41,12.83 253.76,19.48 253.76,23.27 251.53,25.5 250.32,25.5 249.81,24.99 249.81,23.81 249.68,23.69 249.55,23.69 J13.O2
PCIE_B2T_B2_TX_DN<15>: length 38
  TOP w0.127: J14.16 v1(272.19,8.88)
  LYR6 w0.127: v1(272.19,8.88) 271.7,8.39 270.52,8.39 270.15,8.03 270.15,7.22 269.94,7.01 264.09,7.01 263.34,6.25 255.31,6.25 252.67,8.9 252.67,16.51 252.5,16.68 252.31,16.87 252.31,21.88 251.8,22.39 251.55,22.39 J13.N1
PCIE_B2T_B2_TX_DP<0>: length 46.1
  TOP w0.127: J14.117 v1(268.38,25.39)
  BOTTOM w0.127: J13.K8 237.55,19.19 237.8,19.19 238.15,19.54 238.15,26.1 244.7,32.65 255.73,32.65 262.1,26.28 263.39,26.28 264.25,27.14 266.11,27.14 266.33,26.91 266.33,26.2 266.66,25.87 267.9,25.87 v1(268.38,25.39)
PCIE_B2T_B2_TX_DP<1>: length 46.1
  TOP w0.127: J14.102 v1(269.65,22.85)
  BOTTOM w0.127: J13.J7 239.55,17.89 239.88,17.89 240.16,18.16 240.16,26.2 245.39,31.43 254.89,31.43 261.73,24.6 267.38,24.6 267.6,24.37 267.6,23.66 267.93,23.33 269.17,23.33 v1(269.65,22.85)
PCIE_B2T_B2_TX_DP<2>: length 41.3
  TOP w0.127: J14.85 v1(268.38,20.31)
  BOTTOM w0.127: v1(268.38,20.31) 267.9,20.79 266.66,20.79 266.33,21.12 266.33,21.83 266.11,22.06 264.99,22.06 264.35,22.7 261.77,22.7 254.28,30.19 246.36,30.19 242.17,26 242.17,24.69 242.16,24.69 242.16,19.55 241.8,19.19 241.55,19.19 J13.K6
PCIE_B2T_B2_TX_DP<3>: length 42
  TOP w0.127: J14.70 v1(269.65,17.77)
  BOTTOM w0.127: v1(269.65,17.77) 269.17,18.25 267.93,18.25 267.6,18.58 267.6,19.29 267.38,19.52 262.82,19.52 253.42,28.92 253.41,28.92 246.97,28.92 244.15,26.1 244.15,18.23 243.8,17.89 243.55,17.89 J13.J5
PCIE_B2T_B2_TX_DP<4>: length 37.3
  TOP w0.127: J14.53 v1(268.38,15.23)
  BOTTOM w0.127: v1(268.38,15.23) 267.9,15.71 266.66,15.71 266.33,16.04 266.33,16.75 266.11,16.98 264.46,16.98 263.83,17.61 262.59,17.61 252.5,27.7 248.03,27.7 246.15,25.82 246.15,19.56 245.78,19.19 245.55,19.19 J13.K4
PCIE_B2T_B2_TX_DP<5>: length 38
  TOP w0.127: J14.38 v1(269.65,12.69)
  BOTTOM w0.127: J13.J3 247.55,17.89 247.82,17.89 248.16,18.23 248.16,25.97 248.16,25.97 248.16,25.99 248.65,26.48 252,26.48 264.04,14.44 267.38,14.44 267.6,14.21 267.6,13.5 267.93,13.17 269.17,13.17 v1(269.65,12.69)
PCIE_B2T_B2_TX_DP<6>: length 33.1
  TOP w0.127: J14.21 v1(268.38,10.15)
  BOTTOM w0.127: v1(268.38,10.15) 267.9,10.63 266.66,10.63 266.33,10.96 266.33,11.67 266.11,11.9 265.28,11.9 263.98,13.2 263.04,13.2 258.98,17.25 258.66,17.25 251.84,24.08 251.84,24.69 251.35,25.18 250.88,25.18 250.88,25.18 250.6,25.18 250.16,24.75 250.16,19.48 249.86,19.19 249.55,19.19 J13.K2
PCIE_B2T_B2_TX_DP<7>: length 25.2
  TOP w0.127: J14.6 v1(269.65,7.61)
  BOTTOM w0.127: J13.J1 251.55,17.89 254.53,17.89 256.83,15.58 258.7,15.58 261.96,12.32 261.96,11.07 263.67,9.36 267.38,9.36 267.6,9.13 267.6,8.42 267.93,8.09 269.17,8.09 v1(269.65,7.61)
PCIE_B2T_B2_TX_DP<8>: length 44.5
  TOP w0.127: J14.119 v1(270.92,25.39)
  LYR6 w0.127: v1(270.92,25.39) 270.43,25.88 269.16,25.88 268.89,26.15 268.89,26.94 268.68,27.15 264.34,27.15 263.47,26.28 261.08,26.28 255.65,31.71 242.39,31.71 238.16,27.48 238.16,23.76 237.79,23.39 237.55,23.39 J13.N8
PCIE_B2T_B2_TX_DP<9>: length 44.2
  TOP w0.127: J14.104 v1(272.19,22.85)
  LYR6 w0.127: J13.M7 239.55,22.09 239.88,22.09 240.13,22.34 240.13,26.86 243.94,30.67 255.21,30.67 261.27,24.61 269.95,24.61 270.15,24.41 270.15,23.62 270.43,23.34 271.7,23.34 v1(272.19,22.85)
PCIE_B2T_B2_TX_DP<10>: length 39.5
  TOP w0.127: J14.87 v1(270.92,20.31)
  LYR6 w0.127: J13.N6 241.55,23.39 241.91,23.39 242.14,23.62 242.14,26.25 245.52,29.63 253.18,29.63 256.39,26.42 257.97,26.42 261.68,22.71 263.7,22.71 264.34,22.07 268.68,22.07 268.88,21.87 268.88,21.07 269.16,20.8 270.43,20.8 v1(270.92,20.31)
PCIE_B2T_B2_TX_DP<11>: length 40.2
  TOP w0.127: J14.72 v1(272.19,17.77)
  LYR6 w0.127: v1(272.19,17.77) 271.7,18.26 270.43,18.26 270.15,18.53 270.15,19.33 269.96,19.53 261.76,19.53 252.7,28.59 246.54,28.59 244.15,26.19 244.15,22.38 243.86,22.09 243.55,22.09 J13.M5
PCIE_B2T_B2_TX_DP<12>: length 36.3
  TOP w0.127: J14.55 v1(270.92,15.23)
  LYR6 w0.127: v1(270.92,15.23) 270.43,15.72 269.16,15.72 268.89,15.99 268.89,16.78 268.68,16.99 264.68,16.99 264.07,17.6 261.28,17.6 255.94,22.94 255.94,23.82 252.24,27.52 247.45,27.52 246.15,26.23 246.15,23.72 245.82,23.39 245.55,23.39 J13.N4
PCIE_B2T_B2_TX_DP<13>: length 38.1
  TOP w0.127: J14.40 v1(272.19,12.69)
  LYR6 w0.127: J13.M3 247.55,22.09 247.91,22.09 248.16,22.35 248.16,25.99 248.65,26.48 251.71,26.48 254.78,23.41 254.78,20.62 260.39,15.01 263.42,15.01 263.98,14.45 269.95,14.45 270.15,14.25 270.15,13.45 270.43,13.18 271.7,13.18 v1(272.19,12.69)
PCIE_B2T_B2_TX_DP<14>: length 33.4
  TOP w0.127: J14.23 v1(270.92,10.15)
  LYR6 w0.127: J13.N2 249.55,23.39 249.8,23.39 250.1,23.69 250.1,24.87 250.44,25.21 251.4,25.21 253.47,23.15 253.47,19.36 260.29,12.54 263.95,12.54 264.57,11.91 268.68,11.91 268.89,11.7 268.89,10.91 269.16,10.64 270.43,10.64 v1(270.92,10.15)
PCIE_B2T_B2_TX_DP<15>: length 38
  TOP w0.127: J14.8 v1(272.19,7.61)
  LYR6 w0.127: v1(272.19,7.61) 271.7,8.1 270.64,8.1 270.45,7.91 270.45,7.1 270.06,6.72 264.22,6.72 263.46,5.96 255.19,5.96 252.38,8.78 252.38,16.39 252.02,16.75 252.02,21.76 251.68,22.09 251.55,22.09 J13.M1
PCIE_CFG_B1_ID0: length 37.6
  TOP w0.127: J2.149 v1(47.38,30.47)
  LYR4 w0.13: v1(47.38,30.47) 46.78,29.87 46.81,29.85 46.81,27.68 46.53,27.41 43.51,27.41 42.59,26.48 27.62,26.48 27.13,26 27.13,14.27 J1.G3
PCIE_CFG_B1_ID1: length 34.5
  TOP w0.127: J2.148 v1(46.11,30.47)
  LYR4 w0.13: v1(46.11,30.47) 45.41,29.77 45.41,28.98 44.98,28.55 44.19,28.55 43.74,28.1 41.83,28.1 40.63,26.9 27.38,26.9 26.88,26.4 26.88,15.42 J1.H3
PCIE_CFG_B2_ID0: length 37.6
  TOP w0.127: J14.149 v1(268.38,30.47)
  LYR4 w0.13: v1(268.38,30.47) 267.78,29.87 267.81,29.85 267.81,27.68 267.53,27.41 264.51,27.41 263.59,26.48 248.62,26.48 248.13,26 248.13,14.27 J13.G3
PCIE_CFG_B2_ID1: length 34.5
  TOP w0.127: J14.148 v1(267.11,30.47)
  LYR4 w0.13: v1(267.11,30.47) 266.41,29.77 266.41,28.98 265.98,28.55 265.19,28.55 264.74,28.1 262.83,28.1 261.63,26.9 248.38,26.9 247.88,26.4 247.88,15.42 J13.H3
PCIE_RESET_B1_N<0>: length 36.1
  TOP w0.127: J2.150 v1(48.65,30.47)
  LYR4 w0.13: v1(48.65,30.47) 48.06,29.88 48.06,25.11 47.74,24.79 37.69,24.79 36.79,25.69 29.43,25.69 28.85,25.11 28.85,16.69 J1.I2
PCIE_RESET_B1_N<1>: length 41.6
  TOP w0.127: J2.151 v1(49.92,30.47)
  LYR4 w0.13: J1.H2 28,14.44 29.14,15.58 29.14,24.73 29.65,25.23 36.24,25.23 38.57,22.9 43.09,22.9 43.79,22.2 48.94,22.2 49.28,22.55 49.28,29.83 v1(49.92,30.47)
PCIE_RESET_B1_N<2>: length 35.6
  TOP w0.127: J2.143 v1(49.92,29.2)
  LYR4 w0.13: J1.H1 30.92,15.46 30.92,18.3 33.15,20.54 34.25,20.54 35.16,19.62 50.07,19.62 50.6,20.15 50.6,28.52 v1(49.92,29.2)
PCIE_RESET_B1_N<3>: length 43
  TOP w0.127: J2.152 v1(51.19,30.47)
  LYR4 w0.13: J1.G1 31.43,14.57 31.43,18.15 33.5,20.22 34.09,20.22 35.19,19.13 43.23,19.13 43.67,18.68 43.67,17.96 44.48,17.16 51.67,17.16 51.92,17.41 51.92,29.74 v1(51.19,30.47)
PCIE_RESET_B2_N<0>: length 36.1
  TOP w0.127: J14.150 v1(269.65,30.47)
  LYR4 w0.13: v1(269.65,30.47) 269.06,29.88 269.06,25.11 268.74,24.79 258.69,24.79 257.79,25.69 250.43,25.69 249.85,25.11 249.85,16.69 J13.I2
PCIE_RESET_B2_N<1>: length 41.6
  TOP w0.127: J14.151 v1(270.92,30.47)
  LYR4 w0.13: v1(270.92,30.47) 270.28,29.83 270.28,22.55 269.94,22.2 264.79,22.2 264.09,22.9 259.57,22.9 257.24,25.23 250.65,25.23 250.14,24.73 250.14,15.58 249,14.44 J13.H2
PCIE_RESET_B2_N<2>: length 36.2
  TOP w0.102: J14.143 v1(270.92,29.2)
  LYR4 w0.13: v1(270.92,29.2) 271.6,28.52 271.6,20.15 271.07,19.62 262.97,19.62 261.32,21.28 254.89,21.28 251.92,18.3 251.92,15.46 J13.H1
PCIE_RESET_B2_N<3>: length 43.1
  TOP w0.127: J14.152 v1(272.19,30.47)
  LYR4 w0.13: v1(272.19,30.47) 272.92,29.74 272.92,17.41 272.67,17.16 263.61,17.16 259.94,20.83 255.11,20.83 252.43,18.15 252.43,14.57 J13.G1
PCIE_T2B_B1_RX_DN<0>: length 53.3
  TOP w0.127: J2.121 42.45,25.54 41.86,25.54 41.26,26.15 41.26,26.95 35.3,32.91 22.75,32.91 16.85,27.01 16.85,7.08 16.66,6.89 16.55,6.89 J1.C8
PCIE_T2B_B1_RX_DN<1>: length 54.2
  TOP w0.127: J2.106 43.72,23 41.52,23 39.8,24.72 39.8,26.36 39.62,26.53 34.47,31.69 23.93,31.69 18.85,26.61 18.85,5.77 18.67,5.59 18.55,5.59 J1.B7
PCIE_T2B_B1_RX_DN<2>: length 49.6
  TOP w0.127: J1.C6 20.55,6.89 20.67,6.89 20.85,7.06 20.85,26.49 24.82,30.47 33.69,30.47 38.53,25.63 38.53,23.92 41.99,20.46 42.45,20.46 J2.89
PCIE_T2B_B1_RX_DN<3>: length 50.6
  TOP w0.127: J2.74 43.72,17.92 41.79,17.92 37.32,22.39 35.8,23.91 35.8,26.33 32.88,29.25 25.83,29.25 22.84,26.26 22.84,5.76 22.67,5.59 22.55,5.59 J1.B5
PCIE_T2B_B1_RX_DN<4>: length 46
  TOP w0.127: J1.C4 24.55,6.89 24.67,6.89 24.85,7.07 24.85,25.86 27.02,28.03 32.38,28.03 34.35,26.06 34.35,23.58 37.14,20.79 41.1,16.83 41.1,16.45 42.15,15.41 42.48,15.41 J2.57
PCIE_T2B_B1_RX_DN<5>: length 49.6
  TOP w0.127: J1.B3 26.55,5.59 26.67,5.59 26.86,5.77 26.86,26.04 26.86,26.05 26.86,26.11 27.53,26.78 28.47,26.78 31.9,26.78 32.95,25.73 32.95,18.81 34.65,17.11 38.32,17.11 41.17,14.26 41.17,13.48 41.81,12.84 43.72,12.84 J2.42
PCIE_T2B_B1_RX_DN<6>: length 44.6
  TOP w0.127: J2.25 42.45,10.3 41.46,10.3 41.08,10.68 41.08,11.85 40.24,12.68 40.24,13.32 37.8,15.76 34.22,15.76 31.62,18.36 31.62,24.82 30.92,25.52 29.5,25.52 28.86,24.87 28.86,7.07 28.67,6.89 28.55,6.89 J1.C2
PCIE_T2B_B1_RX_DN<7>: length 15.5
  TOP w0.127: J2.10 43.72,7.76 41.46,7.76 39.29,5.59 30.55,5.59 J1.B1
PCIE_T2B_B1_RX_DN<8>: length 50.5
  TOP w0.127: J2.123 v1(44.84,26.66)
  LYR3 w0.127: J1.F8 16.55,11.09 16.68,11.09 16.81,11.21 16.81,12.66 16.84,12.69 16.84,27.03 21.79,31.98 35.97,31.98 41.78,26.17 44.35,26.17 v1(44.84,26.66)
PCIE_T2B_B1_RX_DN<9>: length 51.2
  TOP w0.127: J2.108 v1(46.11,24.12)
  LYR3 w0.127: v1(46.11,24.12) 45.62,23.63 43.52,23.63 42.6,24.55 41.28,24.55 34.88,30.95 22.81,30.95 18.85,26.99 18.85,9.94 18.7,9.79 18.55,9.79 J1.E7
PCIE_T2B_B1_RX_DN<10>: length 47
  TOP w0.127: J2.91 v1(44.84,21.58)
  LYR3 w0.127: J1.F6 20.55,11.09 20.68,11.09 20.84,11.24 20.84,26.31 24.45,29.92 34.19,29.92 38,26.12 38,25.22 42.13,21.09 44.35,21.09 v1(44.84,21.58)
PCIE_T2B_B1_RX_DN<11>: length 47.9
  TOP w0.127: J2.76 v1(46.11,19.04)
  LYR3 w0.127: J1.E5 22.55,9.79 22.76,9.79 22.87,9.89 22.87,26.36 25.39,28.88 33.14,28.88 36.15,25.87 36.15,24.87 41.67,19.36 42.55,19.36 42.72,19.19 43.36,18.55 45.62,18.55 v1(46.11,19.04)
PCIE_T2B_B1_RX_DN<12>: length 44.2
  TOP w0.127: J2.59 v1(44.84,16.5)
  LYR3 w0.127: J1.F4 24.55,11.09 24.68,11.09 24.87,11.27 24.87,26.05 26.65,27.84 32.25,27.84 34.6,25.49 34.6,22.89 41.48,16.01 44.35,16.01 v1(44.84,16.5)
